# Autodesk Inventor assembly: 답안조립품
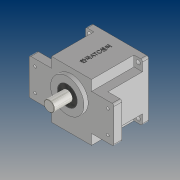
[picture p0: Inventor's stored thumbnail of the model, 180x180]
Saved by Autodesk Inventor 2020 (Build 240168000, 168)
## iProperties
Created: 2020-07
Part Number: 답안조립품
Document SubType Name: Assembly
Designer: PC312-
Author: PC312-
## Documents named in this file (10)
- C:\Users\PC312-\Desktop\700718V1011\답안조립품.iam
- C:\Users\PC312-\Desktop\700718V1011\본체.ipt
- C:\Users\PC312-\Desktop\700718V1011\커버.ipt
- C:\Users\PC312-\Desktop\700718V1011\오일 실 8 22 7.ipt
- C:\Users\PC312-\Desktop\700718V1011\베어링 608.ipt
- C:\Users\PC312-\Desktop\700718V1011\메인 축.ipt
- C:\Users\PC312-\Desktop\700718V1011\서브 축.ipt
- C:\Users\PC312-\Desktop\700718V1011\베어링 6003.ipt
- C:\Users\PC312-\Desktop\700718V1011\오일 실 17 32 8.ipt
- C:\Users\PC312-\Desktop\700718V1011\볼트 M4.ipt
